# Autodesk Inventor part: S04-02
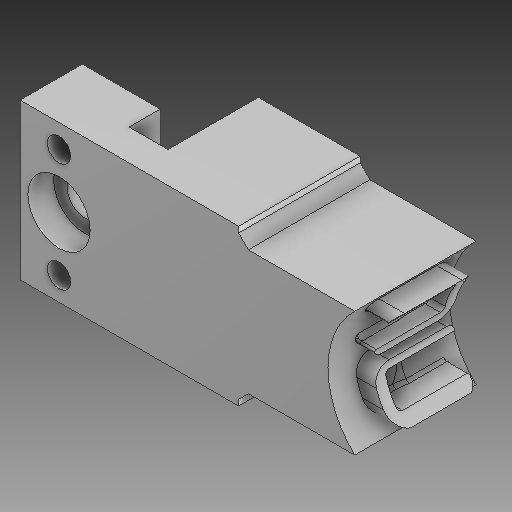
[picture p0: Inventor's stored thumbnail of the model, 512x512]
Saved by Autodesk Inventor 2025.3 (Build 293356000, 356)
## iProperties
Created: 2025-03
Part Number: S04-02
Material: Všeobecné
Document SubType Name: Modeling
Designer: Patrik
Density: 1 g/cm^3
Appearance: Výchozí
Mass: 9.02413 g
Surface Area: 38.9192 cm^2
Volume: 9.02413 cm^3
Stock Number: E 3014_16_20
Description: Jádrová vložka pro posuvný díl
User Status: 1.2343
Sending System: KiM GmbH
Major Version: 4.0
Minor Version: 0.0
Format Version: 0.0
Product Id: KiM GmbH
Hersteller: Meusburger
Material: 1.2343 ESU
Bestellnummer: E 3014/16/20
Teilenummer: E 3014/16/20
Beschreibung: Kerneinsatz für Schieber _ Core for slide
cc_prop_force_one_body: 1
Author: Patrik
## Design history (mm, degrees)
feature "E 3014_16_20_1_1:1"
feature "Vyřezání3"
sketch "Náčrt4"
  geometry: L1 (-5.575, 6.555)-(-5.575, -6.555) reference; A1 r 8.605 centre (0, 0) between (-5.575, 6.555) and (-5.575, -6.555) reference; 1 further point
extrude "Vysunutí4" cut sketch "Náčrt4" stored distance "d6" = 10; taper "d7" = 0 deg
sketch "Náčrt6"
  geometry: L1 (-2.713, 0)-(-2.713, 20) reference; L2 (0, 3.445)-(0, 0) reference; L3 (0, 0)-(30, 0) reference; L4 (30, 0)-(30, 20) reference; L5 (30, 20)-(0, 20) reference; L6 (0, 20)-(0, 16.555) reference; A1 r 8.605 centre (-5.575, 10) between (0, 3.445) and (0, 16.555) reference; 3 further points
extrude "Vysunutí6" cut sketch "Náčrt6" stored distance "d10" = 10; taper "d11" = 0 deg
feature "Vyřezání5"
node "Těleso1"
node "Promítnutá smyčka4"
node "Referenční1"
node "Promítnutá smyčka5"
feature "Plocha4"
node "Povrch4"
feature "Plocha6"
node "Povrch6"
